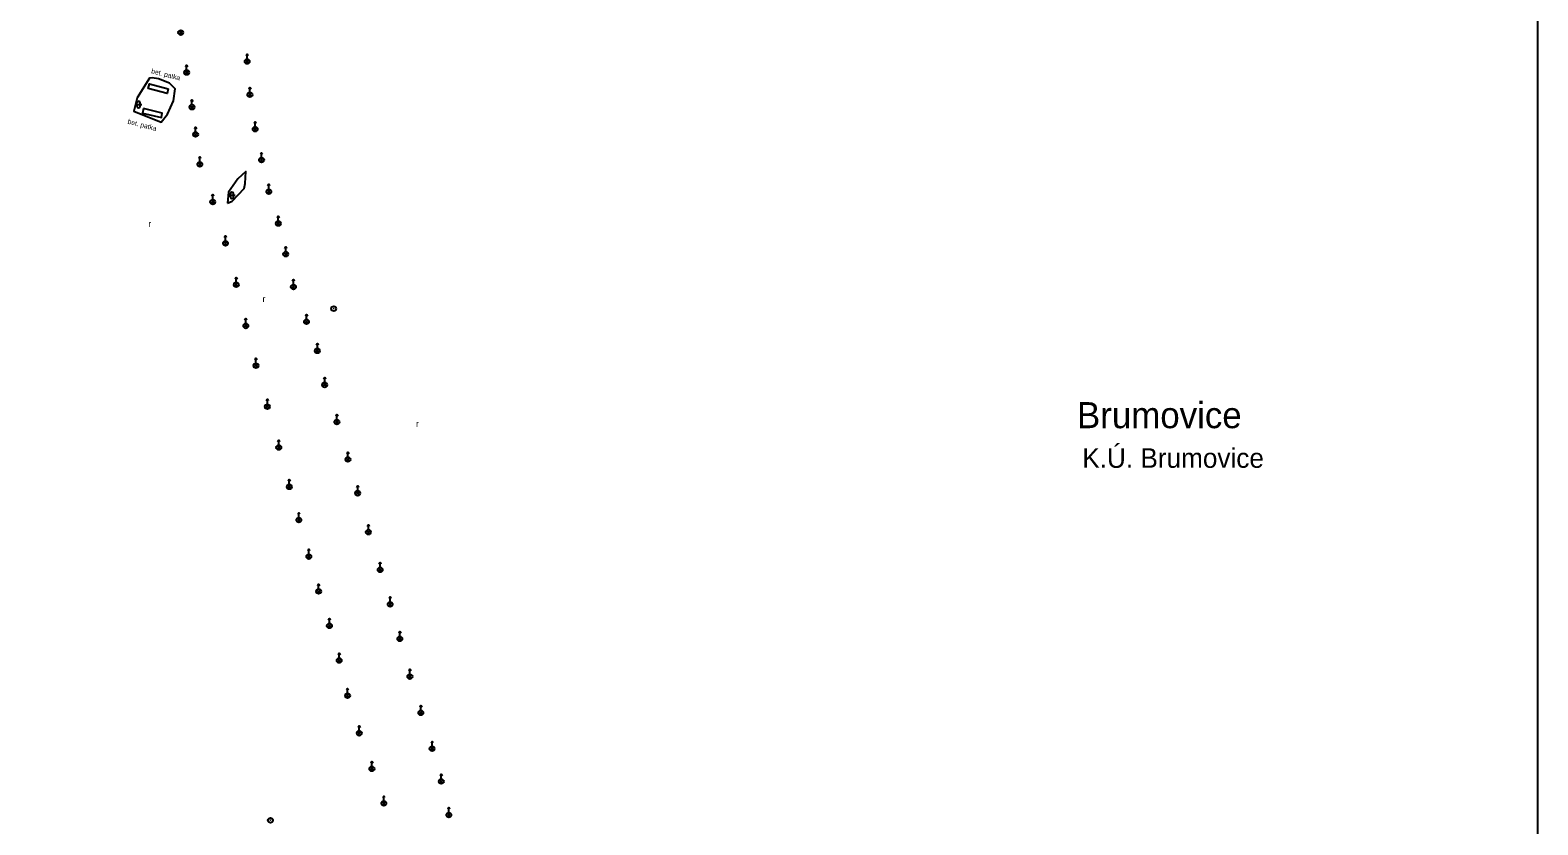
# Model space of a CAD drawing. Extents: x -582188 to -561562, y -1187250 to -1183500.
# Drawn here: x -580231.3 to -580000, y -1186877 to -1186755.1 of the extents above; entities that cross this region are included whole.
import ezdxf

# ---------------------------------------------------------------- set-up
doc = ezdxf.new("R2010")
doc.units = 0
for name, color, linetype in [('MAP_ZN_BP', 7, 'Continuous'), ('NÁZEV_K_Ú', 7, 'Continuous'), ('NÁZVY_SÍDEL_JEDNOTKY', 7, 'Continuous'), ('POMOC_POPIS', 7, 'Continuous'), ('ROZHRANÍ_PLOCH', 7, 'Continuous'), ('RÁMY_ML', 7, 'Continuous'), ('ZELEŇ', 7, 'Continuous'), ('ZN_BP', 7, 'Continuous'), ('ZN_KULTUR', 7, 'Continuous')]:
    doc.layers.add(name, color=color, linetype=linetype)

msp = doc.modelspace()

# ---------------------------------------------------------------- linework, layer by layer
at = {"layer": 'MAP_ZN_BP'}
for centre, radius in [((-580184.73, -1186797.791), 0.375), ((-580184.73, -1186797.791), 0.0005), ((-580194.44, -1186876.291), 0.375), ((-580194.44, -1186876.291), 0.0005)]:
    msp.add_circle(centre, radius, dxfattribs=at)
at = {"layer": 'ROZHRANÍ_PLOCH'}
for points in [[(-580210.11, -1186764.06), (-580210.3, -1186764.78), (-580213.19, -1186764.01), (-580213.01, -1186763.31), (-580210.11, -1186764.06)], [(-580213.91, -1186767.11), (-580214.05, -1186767.81), (-580211.16, -1186768.48), (-580211.06, -1186767.79), (-580213.91, -1186767.11)]]:
    msp.add_lwpolyline(points, dxfattribs=at)
at = {"layer": 'RÁMY_ML'}
msp.add_lwpolyline([(-580000, -1187000), (-580000, -1186750), (-580312.5, -1186750), (-580312.5, -1186500), (-580000, -1186500), (-580000, -1186750)], dxfattribs=at)
at = {"layer": 'ZELEŇ'}
for points in [[(-580211.63, -1186762.55), (-580212.57, -1186762.37), (-580213, -1186762.42), (-580214.88, -1186765.46), (-580215.37, -1186767.51), (-580211.22, -1186769.19), (-580210.24, -1186767.93), (-580209.32, -1186765.9), (-580209.06, -1186764.05), (-580209.92, -1186763.19), (-580211.63, -1186762.55)], [(-580201.02, -1186781.6), (-580200.33, -1186781.32), (-580198.46, -1186779.35), (-580198.29, -1186778.57), (-580198.2, -1186776.75), (-580199.45, -1186777.85), (-580200.88, -1186779.93), (-580201.02, -1186781.6)]]:
    msp.add_lwpolyline(points, dxfattribs=at)
at = {"layer": 'ZN_BP'}
for p, q in [((-580208.465, -1186755.704), (-580207.936, -1186755.176)), ((-580207.936, -1186755.708), (-580208.465, -1186755.176)), ((-580207.29, -1186761.185), (-580207.29, -1186760.435)), ((-580198.275, -1186760.144), (-580197.746, -1186759.616)), ((-580197.746, -1186760.148), (-580198.275, -1186759.616)), ((-580198.01, -1186759.505), (-580198.01, -1186758.755)), ((-580207.555, -1186761.824), (-580207.026, -1186761.296)), ((-580207.026, -1186761.828), (-580207.555, -1186761.296)), ((-580197.855, -1186765.234), (-580197.326, -1186764.706)), ((-580197.326, -1186765.238), (-580197.855, -1186764.706)), ((-580197.59, -1186764.595), (-580197.59, -1186763.845)), ((-580206.745, -1186767.134), (-580206.216, -1186766.606)), ((-580206.216, -1186767.138), (-580206.745, -1186766.606)), ((-580206.48, -1186766.495), (-580206.48, -1186765.745)), ((-580196.78, -1186769.875), (-580196.78, -1186769.125)), ((-580206.185, -1186771.324), (-580205.656, -1186770.796)), ((-580205.656, -1186771.328), (-580206.185, -1186770.796)), ((-580205.92, -1186770.685), (-580205.92, -1186769.935)), ((-580197.045, -1186770.514), (-580196.516, -1186769.986)), ((-580196.516, -1186770.518), (-580197.045, -1186769.986)), ((-580195.8, -1186774.615), (-580195.8, -1186773.865)), ((-580205.535, -1186775.914), (-580205.006, -1186775.386)), ((-580205.006, -1186775.918), (-580205.535, -1186775.386)), ((-580205.27, -1186775.275), (-580205.27, -1186774.525)), ((-580196.065, -1186775.254), (-580195.536, -1186774.726)), ((-580195.536, -1186775.258), (-580196.065, -1186774.726)), ((-580194.69, -1186779.465), (-580194.69, -1186778.715)), ((-580203.555, -1186781.684), (-580203.026, -1186781.156)), ((-580203.026, -1186781.688), (-580203.555, -1186781.156)), ((-580203.29, -1186781.045), (-580203.29, -1186780.295)), ((-580194.955, -1186780.104), (-580194.426, -1186779.576)), ((-580194.426, -1186780.108), (-580194.955, -1186779.576)), ((-580193.495, -1186784.994), (-580192.966, -1186784.466)), ((-580192.966, -1186784.998), (-580193.495, -1186784.466)), ((-580193.23, -1186784.355), (-580193.23, -1186783.605)), ((-580201.605, -1186788.034), (-580201.076, -1186787.506)), ((-580201.076, -1186788.038), (-580201.605, -1186787.506)), ((-580201.34, -1186787.395), (-580201.34, -1186786.645)), ((-580192.355, -1186789.684), (-580191.826, -1186789.156)), ((-580191.826, -1186789.688), (-580192.355, -1186789.156)), ((-580192.09, -1186789.045), (-580192.09, -1186788.295)), ((-580199.945, -1186794.384), (-580199.416, -1186793.856)), ((-580199.416, -1186794.388), (-580199.945, -1186793.856)), ((-580199.68, -1186793.745), (-580199.68, -1186792.995)), ((-580191.175, -1186794.724), (-580190.646, -1186794.196)), ((-580190.646, -1186794.728), (-580191.175, -1186794.196)), ((-580190.91, -1186794.085), (-580190.91, -1186793.335)), ((-580198.22, -1186800.065), (-580198.22, -1186799.315)), ((-580189.165, -1186800.064), (-580188.636, -1186799.536)), ((-580188.636, -1186800.068), (-580189.165, -1186799.536)), ((-580188.9, -1186799.425), (-580188.9, -1186798.675)), ((-580198.485, -1186800.704), (-580197.956, -1186800.176)), ((-580197.956, -1186800.708), (-580198.485, -1186800.176)), ((-580187.505, -1186804.534), (-580186.976, -1186804.006)), ((-580186.976, -1186804.538), (-580187.505, -1186804.006)), ((-580187.24, -1186803.895), (-580187.24, -1186803.145)), ((-580196.925, -1186806.794), (-580196.396, -1186806.266)), ((-580196.396, -1186806.798), (-580196.925, -1186806.266)), ((-580196.66, -1186806.155), (-580196.66, -1186805.405)), ((-580186.11, -1186809.115), (-580186.11, -1186808.365)), ((-580186.375, -1186809.754), (-580185.846, -1186809.226)), ((-580185.846, -1186809.758), (-580186.375, -1186809.226)), ((-580195.175, -1186813.084), (-580194.646, -1186812.556)), ((-580194.646, -1186813.088), (-580195.175, -1186812.556)), ((-580194.91, -1186812.445), (-580194.91, -1186811.695)), ((-580184.505, -1186815.444), (-580183.976, -1186814.916)), ((-580183.976, -1186815.448), (-580184.505, -1186814.916)), ((-580184.24, -1186814.805), (-580184.24, -1186814.055)), ((-580193.16, -1186818.725), (-580193.16, -1186817.975)), ((-580193.425, -1186819.364), (-580192.896, -1186818.836)), ((-580192.896, -1186819.368), (-580193.425, -1186818.836)), ((-580182.55, -1186820.545), (-580182.55, -1186819.795)), ((-580182.815, -1186821.184), (-580182.286, -1186820.656)), ((-580182.286, -1186821.188), (-580182.815, -1186820.656)), ((-580191.805, -1186825.394), (-580191.276, -1186824.866)), ((-580191.276, -1186825.398), (-580191.805, -1186824.866)), ((-580191.54, -1186824.755), (-580191.54, -1186824.005)), ((-580181.05, -1186825.735), (-580181.05, -1186824.985)), ((-580181.315, -1186826.374), (-580180.786, -1186825.846)), ((-580180.786, -1186826.378), (-580181.315, -1186825.846)), ((-580190.09, -1186829.845), (-580190.09, -1186829.095)), ((-580190.355, -1186830.484), (-580189.826, -1186829.956)), ((-580189.826, -1186830.488), (-580190.355, -1186829.956)), ((-580179.675, -1186832.334), (-580179.146, -1186831.806)), ((-580179.146, -1186832.338), (-580179.675, -1186831.806)), ((-580179.41, -1186831.695), (-580179.41, -1186830.945)), ((-580188.815, -1186836.094), (-580188.286, -1186835.566)), ((-580188.286, -1186836.098), (-580188.815, -1186835.566)), ((-580188.55, -1186835.455), (-580188.55, -1186834.705)), ((-580177.61, -1186837.475), (-580177.61, -1186836.725)), ((-580177.875, -1186838.114), (-580177.346, -1186837.586)), ((-580177.346, -1186838.118), (-580177.875, -1186837.586)), ((-580187.305, -1186841.434), (-580186.776, -1186840.906)), ((-580186.776, -1186841.438), (-580187.305, -1186840.906)), ((-580187.04, -1186840.795), (-580187.04, -1186840.045)), ((-580176.335, -1186843.414), (-580175.806, -1186842.886)), ((-580175.806, -1186843.418), (-580176.335, -1186842.886)), ((-580176.07, -1186842.775), (-580176.07, -1186842.025)), ((-580185.39, -1186846.065), (-580185.39, -1186845.315)), ((-580185.655, -1186846.704), (-580185.126, -1186846.176)), ((-580185.126, -1186846.708), (-580185.655, -1186846.176)), ((-580174.845, -1186848.714), (-580174.316, -1186848.186)), ((-580174.316, -1186848.718), (-580174.845, -1186848.186)), ((-580174.58, -1186848.075), (-580174.58, -1186847.325)), ((-580183.89, -1186851.385), (-580183.89, -1186850.635)), ((-580184.155, -1186852.024), (-580183.626, -1186851.496)), ((-580183.626, -1186852.028), (-580184.155, -1186851.496)), ((-580173.305, -1186854.504), (-580172.776, -1186853.976)), ((-580172.776, -1186854.508), (-580173.305, -1186853.976)), ((-580173.04, -1186853.865), (-580173.04, -1186853.115)), ((-580182.865, -1186857.434), (-580182.336, -1186856.906)), ((-580182.336, -1186857.438), (-580182.865, -1186856.906)), ((-580182.6, -1186856.795), (-580182.6, -1186856.045)), ((-580171.625, -1186860.054), (-580171.096, -1186859.526)), ((-580171.096, -1186860.058), (-580171.625, -1186859.526)), ((-580171.36, -1186859.415), (-580171.36, -1186858.665)), ((-580180.81, -1186862.555), (-580180.81, -1186861.805)), ((-580181.075, -1186863.194), (-580180.546, -1186862.666)), ((-580180.546, -1186863.198), (-580181.075, -1186862.666)), ((-580169.64, -1186864.925), (-580169.64, -1186864.175)), ((-580169.905, -1186865.564), (-580169.376, -1186865.036)), ((-580169.376, -1186865.568), (-580169.905, -1186865.036)), ((-580179.135, -1186868.664), (-580178.606, -1186868.136)), ((-580178.606, -1186868.668), (-580179.135, -1186868.136)), ((-580178.87, -1186868.025), (-580178.87, -1186867.275)), ((-580168.495, -1186870.584), (-580167.966, -1186870.056)), ((-580167.966, -1186870.588), (-580168.495, -1186870.056)), ((-580168.23, -1186869.945), (-580168.23, -1186869.195)), ((-580177.315, -1186873.954), (-580176.786, -1186873.426)), ((-580176.786, -1186873.958), (-580177.315, -1186873.426)), ((-580177.05, -1186873.315), (-580177.05, -1186872.565)), ((-580167.335, -1186875.734), (-580166.806, -1186875.206)), ((-580166.806, -1186875.738), (-580167.335, -1186875.206)), ((-580167.07, -1186875.095), (-580167.07, -1186874.345))]:
    msp.add_line(p, q, dxfattribs=at)
for points in [[(-580207.415, -1186760.685), (-580207.29, -1186760.435), (-580207.165, -1186760.685)], [(-580198.135, -1186759.005), (-580198.01, -1186758.755), (-580197.885, -1186759.005)], [(-580197.715, -1186764.095), (-580197.59, -1186763.845), (-580197.465, -1186764.095)], [(-580206.605, -1186765.995), (-580206.48, -1186765.745), (-580206.355, -1186765.995)], [(-580196.905, -1186769.375), (-580196.78, -1186769.125), (-580196.655, -1186769.375)], [(-580206.045, -1186770.185), (-580205.92, -1186769.935), (-580205.795, -1186770.185)], [(-580195.925, -1186774.115), (-580195.8, -1186773.865), (-580195.675, -1186774.115)], [(-580205.395, -1186774.775), (-580205.27, -1186774.525), (-580205.145, -1186774.775)], [(-580194.815, -1186778.965), (-580194.69, -1186778.715), (-580194.565, -1186778.965)], [(-580203.415, -1186780.545), (-580203.29, -1186780.295), (-580203.165, -1186780.545)], [(-580193.355, -1186783.855), (-580193.23, -1186783.605), (-580193.105, -1186783.855)], [(-580201.465, -1186786.895), (-580201.34, -1186786.645), (-580201.215, -1186786.895)], [(-580192.215, -1186788.545), (-580192.09, -1186788.295), (-580191.965, -1186788.545)], [(-580199.805, -1186793.245), (-580199.68, -1186792.995), (-580199.555, -1186793.245)], [(-580191.035, -1186793.585), (-580190.91, -1186793.335), (-580190.785, -1186793.585)], [(-580198.345, -1186799.565), (-580198.22, -1186799.315), (-580198.095, -1186799.565)], [(-580189.025, -1186798.925), (-580188.9, -1186798.675), (-580188.775, -1186798.925)], [(-580187.365, -1186803.395), (-580187.24, -1186803.145), (-580187.115, -1186803.395)], [(-580196.785, -1186805.655), (-580196.66, -1186805.405), (-580196.535, -1186805.655)], [(-580186.235, -1186808.615), (-580186.11, -1186808.365), (-580185.985, -1186808.615)], [(-580195.035, -1186811.945), (-580194.91, -1186811.695), (-580194.785, -1186811.945)], [(-580184.365, -1186814.305), (-580184.24, -1186814.055), (-580184.115, -1186814.305)], [(-580193.285, -1186818.225), (-580193.16, -1186817.975), (-580193.035, -1186818.225)], [(-580182.675, -1186820.045), (-580182.55, -1186819.795), (-580182.425, -1186820.045)], [(-580191.665, -1186824.255), (-580191.54, -1186824.005), (-580191.415, -1186824.255)], [(-580181.175, -1186825.235), (-580181.05, -1186824.985), (-580180.925, -1186825.235)], [(-580190.215, -1186829.345), (-580190.09, -1186829.095), (-580189.965, -1186829.345)], [(-580179.535, -1186831.195), (-580179.41, -1186830.945), (-580179.285, -1186831.195)], [(-580188.675, -1186834.955), (-580188.55, -1186834.705), (-580188.425, -1186834.955)], [(-580177.735, -1186836.975), (-580177.61, -1186836.725), (-580177.485, -1186836.975)], [(-580187.165, -1186840.295), (-580187.04, -1186840.045), (-580186.915, -1186840.295)], [(-580176.195, -1186842.275), (-580176.07, -1186842.025), (-580175.945, -1186842.275)], [(-580185.515, -1186845.565), (-580185.39, -1186845.315), (-580185.265, -1186845.565)], [(-580174.705, -1186847.575), (-580174.58, -1186847.325), (-580174.455, -1186847.575)], [(-580184.015, -1186850.885), (-580183.89, -1186850.635), (-580183.765, -1186850.885)], [(-580173.165, -1186853.365), (-580173.04, -1186853.115), (-580172.915, -1186853.365)], [(-580182.725, -1186856.295), (-580182.6, -1186856.045), (-580182.475, -1186856.295)], [(-580171.485, -1186858.915), (-580171.36, -1186858.665), (-580171.235, -1186858.915)], [(-580180.935, -1186862.055), (-580180.81, -1186861.805), (-580180.685, -1186862.055)], [(-580169.765, -1186864.425), (-580169.64, -1186864.175), (-580169.515, -1186864.425)], [(-580178.995, -1186867.525), (-580178.87, -1186867.275), (-580178.745, -1186867.525)], [(-580168.355, -1186869.445), (-580168.23, -1186869.195), (-580168.105, -1186869.445)], [(-580177.175, -1186872.815), (-580177.05, -1186872.565), (-580176.925, -1186872.815)], [(-580167.195, -1186874.595), (-580167.07, -1186874.345), (-580166.945, -1186874.595)]]:
    msp.add_lwpolyline(points, dxfattribs=at)
for centre in [(-580208.2, -1186755.44), (-580198.01, -1186759.88), (-580207.29, -1186761.56), (-580197.59, -1186764.97), (-580206.48, -1186766.87), (-580205.92, -1186771.06), (-580196.78, -1186770.25), (-580205.27, -1186775.65), (-580195.8, -1186774.99), (-580203.29, -1186781.42), (-580194.69, -1186779.84), (-580193.23, -1186784.73), (-580201.34, -1186787.77), (-580192.09, -1186789.42), (-580199.68, -1186794.12), (-580190.91, -1186794.46), (-580188.9, -1186799.8), (-580198.22, -1186800.44), (-580187.24, -1186804.27), (-580196.66, -1186806.53), (-580186.11, -1186809.49), (-580194.91, -1186812.82), (-580184.24, -1186815.18), (-580193.16, -1186819.1), (-580182.55, -1186820.92), (-580191.54, -1186825.13), (-580181.05, -1186826.11), (-580190.09, -1186830.22), (-580179.41, -1186832.07), (-580188.55, -1186835.83), (-580177.61, -1186837.85), (-580187.04, -1186841.17), (-580176.07, -1186843.15), (-580185.39, -1186846.44), (-580174.58, -1186848.45), (-580183.89, -1186851.76), (-580173.04, -1186854.24), (-580182.6, -1186857.17), (-580171.36, -1186859.79), (-580180.81, -1186862.93), (-580169.64, -1186865.3), (-580178.87, -1186868.4), (-580168.23, -1186870.32), (-580177.05, -1186873.69), (-580167.07, -1186875.47)]:
    msp.add_circle(centre, 0.375, dxfattribs=at)
at = {"layer": 'ZN_KULTUR'}
for p, q in [((-580215.17, -1186766.48), (-580214.17, -1186766.48)), ((-580214.92, -1186766.73), (-580214.92, -1186766.23)), ((-580214.42, -1186766.73), (-580214.42, -1186766.23)), ((-580200.84, -1186780.4), (-580199.84, -1186780.4)), ((-580200.59, -1186780.65), (-580200.59, -1186780.15)), ((-580200.09, -1186780.65), (-580200.09, -1186780.15))]:
    msp.add_line(p, q, dxfattribs=at)
for centre, start, end in [((-580214.67, -1186766.23), 0, 179.99999), ((-580214.67, -1186766.73), 179.99999, 359.99999), ((-580200.34, -1186780.15), 0, 179.99999), ((-580200.34, -1186780.65), 179.99999, 359.99999)]:
    msp.add_arc(centre, 0.25, start, end, dxfattribs=at)

# ---------------------------------------------------------------- texts
at = {"layer": 'NÁZEV_K_Ú'}
msp.add_text('K.Ú. Brumovice', height=3, dxfattribs=at).set_placement((-580069.89, -1186822.21))
at = {"layer": 'NÁZVY_SÍDEL_JEDNOTKY'}
msp.add_text('Brumovice', height=4, dxfattribs=at).set_placement((-580070.7, -1186816.13))
at = {"layer": 'POMOC_POPIS'}
for p in [(-580212.78, -1186761.65), (-580216.41, -1186769.4)]:
    msp.add_text('bet. patka', height=0.75, rotation=345.49983, dxfattribs=at).set_placement(p)
at = {"layer": 'ZN_KULTUR'}
for p in [(-580213.178, -1186785.272), (-580195.658, -1186796.772), (-580172.118, -1186815.942)]:
    msp.add_text('r', height=1, dxfattribs=at).set_placement(p)

doc.saveas('drawing.dxf')
